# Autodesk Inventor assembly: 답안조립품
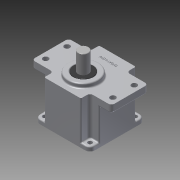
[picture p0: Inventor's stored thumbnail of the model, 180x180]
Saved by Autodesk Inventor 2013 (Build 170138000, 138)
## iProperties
Created: 2015-07
Part Number: 답안조립품
Document SubType Name: Assembly
Designer: user
Author: user
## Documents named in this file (12)
- C:\Users\user\Desktop\450734V1013\답안조립품.iam
- C:\Users\user\Desktop\450734V1013\메인축.ipt
- C:\Users\user\Desktop\450734V1013\베어링 608.ipt
- 베어링 608.ipt
- C:\Users\user\Desktop\450734V1013\커버.ipt
- C:\Users\user\Desktop\450734V1013\서브축.ipt
- C:\Users\user\Desktop\450734V1013\베어링 6003.ipt
- 베어링 6003.ipt
- C:\Users\user\Desktop\450734V1013\본체.ipt
- C:\Users\user\Desktop\450734V1013\오일실 17x32x8.ipt
- C:\Users\user\Desktop\450734V1013\오일실 8x22x7.ipt
- C:\Users\user\Desktop\450734V1013\M4x0.5x16.ipt
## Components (4 placed, 1 different names)
1. M4x0.5x12:1
2. M4x0.5x12:2
3. M4x0.5x12:3
4. M4x0.5x12:4
